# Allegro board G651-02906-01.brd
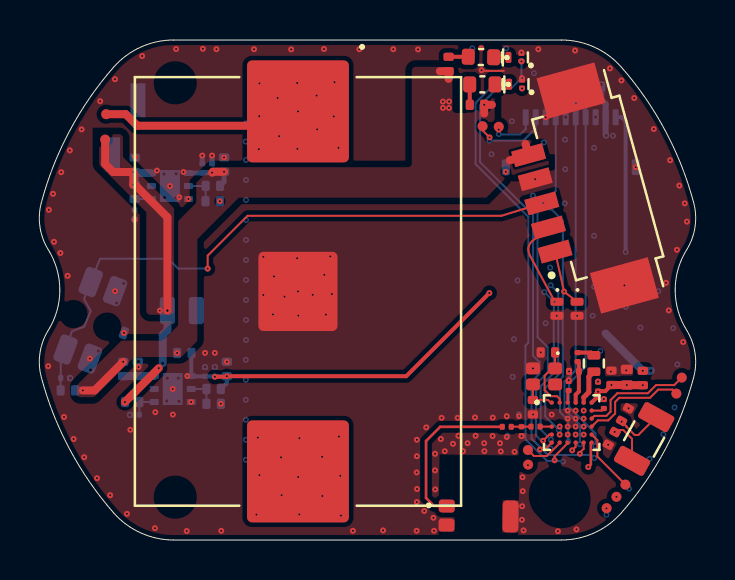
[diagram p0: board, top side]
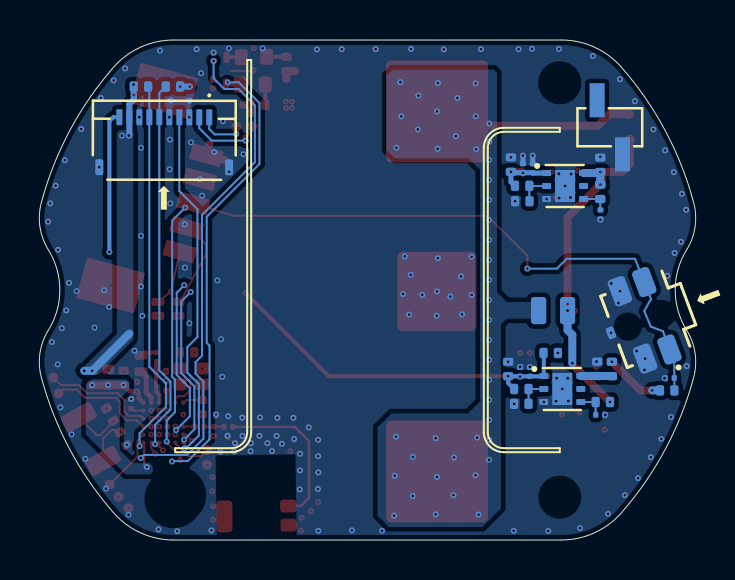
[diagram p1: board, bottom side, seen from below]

Outline 32.79 x 25 mm; copper layers: TOP, L2, L3, BOTTOM. Coordinates in mm from the lower left corner of the outline.
Outline path: 0.07,16.87 arc(1.49,20.46) 3.68,23.64 arc(5.04,24.64) 6.69,25 26.1,25 arc(27.75,24.64) 29.11,23.64 arc(31.3,20.46) 32.72,16.87 arc(32.79,15.65) 32.37,14.51 arc(31.79,12.5) 32.37,10.49 arc(32.79,9.35) 32.72,8.13 arc(31.3,4.54) 29.11,1.36 arc(27.75,0.36) 26.1,0 6.69,0 arc(5.04,0.36) 3.68,1.36 arc(1.49,4.54) 0.07,8.13 arc(0,9.35) 0.42,10.49 arc(0.99,12.5) 0.42,14.51 arc(0,15.65) 0.07,16.87

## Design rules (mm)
constraint set DEFAULT: min track width 0.1
net group 50_OHMS: nets MCU_ANT_OUT
net group HIGH_CURRENT_POWER: nets MCU_DCC MCU_DCC1 MCU_DEC4 PP3300_SENSORS_R
net group MODERATE_CURRENT_POWER: nets LED_STATUS1 LED_STATUS1_R LED_STATUS2 LED_STATUS2_R PP1800_SENSORS
nets with their own width: min track width 0.1; nets MCU_ANT_IN
nets with their own width: min track width 0.4; nets PP3300_SENSORS_MCU

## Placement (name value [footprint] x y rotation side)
A1  -  [ANT_325X165X115_W3008]  21.95 1.2 359.2 top
C1  12pF  [CAPC1005L]  29.28 6.27 241 top
C2  12pF  [CAPC1005L]  28.61 5.08 61.7 top
C5  0.1uF  [CAPC0603L]  28.22 6.8 90 top
C6  1uF  [CAPC0603L_TOL09]  26.73 8.43 180 top
C7  100pF  [CAPC0603L]  26.46 7.7 90 top
C8  12pF  [CAPC1005L]  25.42 9.38 180 top
C9  12pF  [CAPC1005L]  24.67 6.64 270 top
C10  1.2pF  [CAPC0603L]  24.1 5.44 270 top
C12  1uF  [CAPC1005L]  4.74 18.76 90 bottom
C13  1uF  [CAPC1005L]  9.21 18.77 90 bottom
C15  1uF  [CAPC1005L]  9.35 8.55 90 bottom
C16  1000pF  [CAPC0603L]  1.26 8.1 359.2 bottom
C17  4.7uF  [CAPC1005L_TOL15]  29.37 8.14 90 top
C18  1uF  [CAPC1005L]  28.6 8.11 90 top
C19  0.1uF  [CAPC0603L]  27.93 7.67 90 top
C20  0.1uF  [CAPC0603L]  8.61 18.59 90 bottom
C21  0.01uF  [CAPC0603L]  8.12 18.59 90 bottom
C22  0.1uF  [CAPC0603L]  8.75 8.41 90 bottom
C23  0.01uF  [CAPC0603L]  8.26 8.41 90 bottom
C24  1uF  [CAPC1005L]  4.89 8.56 90 bottom
D1  -  [SOD110X70X60L_SP1212]  25.87 11.56 270 top
D2  -  [SOD110X70X60L_SP1212]  26.88 11.56 270 top
DS1  GREEN  [LEDC1608L_TOL25]  22.14 22.78 180 top
DS2  GREEN  [LEDC1608L_TOL25]  22.07 24.15 178.8 top
J1  -  [KEYSTONE_3034TR]  12.91 12.43 270 top
J2  -  [MOLEX_53261-0571]  27.92 17.6 285.3 top
J3  -  [HIROSE_FH34SRJ-10S-0P5SH-50]  26.57 19.99 0.1 bottom
J4  -  [HARWIN_M50-3140245]  4.27 20.64 180 bottom
L1  15nH  [INDC0603L]  26.91 9.14 270 top
L2  10uH  [INDC1107L_TOL10]  27.72 8.83 90 top
L3  2.2nH  [INDC0603L]  24.8 5.67 180 top
L4  3.3nH  [INDC0603L]  23.36 5.66 180 top
NOREF  -  []  4.59 18.6 0 top
NOREF#2  -  []  10.36 0.88 90 top
NOREF#3  -  []  0.87 7.21 0 top
NOREF#4  -  []  0.91 8.02 0 top
NOREF#5  -  []  5.72 6.9 90 top
NOREF#6  -  []  28.09 6.95 0 top
NOREF#7  -  []  8.2 10.75 90 top
NOREF#8  -  []  4.47 19.29 0 top
NOREF#9  -  []  28.04 7.95 0 top
NOREF#10  -  []  27.17 22.51 0 top
NOREF#11  -  []  21.22 22.26 90 top
NOREF#12  -  []  7.96 18.91 0 top
NOREF#13  -  []  24.11 6.48 0 top
NOREF#14  -  []  25.78 14.42 0 top
NOREF#15  -  []  26.34 8.25 0 top
NOREF#16  -  []  23.25 23.8 90 top
NOREF#17  -  []  1.68 11.3 0 top
NOREF#18  -  []  6.7 9.62 0 top
NOREF#19  -  []  14.46 10.45 90 top
NOREF#20  -  []  28.31 21.14 0 top
NOREF#21  -  []  2.65 19.69 0 top
NOREF#22  -  []  4.47 17.93 0 top
NOREF#23  -  []  7 16.9 90 top
NOREF#24  -  []  23.94 -0.03 90 top
NOREF#25  -  []  28.05 4.92 0 top
NOREF#26  -  []  26.63 8.25 0 top
NOREF#27  -  []  8.17 7.08 0 top
NOREF#28  -  []  8.92 8.09 90 top
NOREF#29  -  []  21.35 21.48 90 top
NOREF#30  -  []  27.49 11.21 90 top
NOREF#31  -  []  9.2 8.39 0 top
NOREF#32  -  []  26.78 8.84 0 top
NOREF#33  -  []  29.27 5.68 90 top
NOREF#34  -  []  4.43 6.09 90 top
NOREF#35  -  []  7.75 9.07 90 top
NOREF#36  -  []  24.38 7.53 90 top
NOREF#37  -  []  25.98 22.51 0 top
NOREF#38  -  []  23.57 0.35 90 top
NOREF#39  -  []  23.92 16.1 0 top
NOREF#40  -  []  23.27 5.58 0 top
NOREF#41  -  []  28.46 4.92 0 top
NOREF#42  -  []  27.92 14.6 0 top
NOREF#43  -  []  6.14 6.75 0 top
NOREF#44  -  []  30.14 18.02 90 top
NOREF#45  -  []  9.06 18.61 0 top
NOREF#46  -  []  8.13 7.39 0 top
NOREF#47  -  []  4.59 17.25 0 top
NOREF#48  -  []  26.33 7.84 0 top
NOREF#49  -  []  5.8 16.96 0 top
NOREF#50  -  []  26.33 7.39 0 top
NOREF#51  -  []  24.46 19.24 0 top
NOREF#52  -  []  4.43 6.09 0 top
NOREF#53  -  []  5.58 17.05 90 top
NOREF#54  -  []  23.97 5.58 0 top
NOREF#55  -  []  23.28 22.46 90 top
NOREF#56  -  []  26.66 22.39 90 top
NOREF#57  -  []  7.77 6.75 90 top
NOREF#58  -  []  0.49 9.82 0 top
NOREF#59  -  []  26.53 12.11 0 top
NOREF#60  -  []  4.33 8.4 0 top
NOREF#61  -  []  30.82 15.5 90 top
NOREF#62  -  []  20.3 23.64 0 top
NOREF#63  -  []  30.14 18.02 90 top
NOREF#64  -  []  8.48 18.29 0 top
NOREF#65  -  []  8.78 18.27 90 top
NOREF#66  -  []  25.52 12.11 0 top
NOREF#67  -  []  8.54 6.65 0 top
NOREF#68  -  []  24.43 7.58 0 top
NOREF#69  -  []  27.51 9.2 0 top
NOREF#70  -  []  24.68 8.58 0 top
NOREF#71  -  []  8.48 18.73 0 top
NOREF#72  -  []  4.6 15.97 0 top
NOREF#73  -  []  9.08 9.07 0 top
NOREF#74  -  []  26.33 11.23 90 top
NOREF#75  -  []  20.73 23.27 90 top
NOREF#76  -  []  26.39 8.62 0 top
NOREF#77  -  []  27.77 7.99 0 top
NOREF#78  -  []  24.46 19.24 0 top
NOREF#79  -  []  8.13 6.65 0 top
NOREF#80  -  []  25.61 22.95 0 top
NOREF#81  -  []  30.14 18.02 90 top
NOREF#82  -  []  28.79 5.94 0 top
NOREF#83  -  []  26.3 8.02 0 top
NOREF#84  -  []  4.9 15.96 90 top
NOREF#85  -  []  24.9 9.11 90 top
NOREF#86  -  []  25.5 4.87 0 top
NOREF#87  -  []  8.09 17.55 0 top
NOREF#88  -  []  4.62 8.04 90 top
NOREF#89  -  []  28.1 8.23 90 top
NOREF#90  -  []  19.89 23.64 0 top
NOREF#91  -  []  8.43 8.09 90 top
NOREF#92  -  []  27.21 22.39 0 top
NOREF#93  -  []  5.94 6.81 0 top
NOREF#94  -  []  25.61 5.27 0 top
NOREF#95  -  []  4.57 15.96 0 top
NOREF#96  -  []  29.11 5.41 90 top
NOREF#97  -  []  39.01 18.06 90 top
NOREF#98  -  []  5.89 19.69 90 top
NOREF#99  -  []  8.54 7.39 0 top
NOREF#100  -  []  8.94 18.25 90 top
NOREF#101  -  []  29.12 18.91 90 top
NOREF#102  -  []  4.6 16.43 0 top
NOREF#103  -  []  1.24 7.32 0 top
NOREF#104  -  []  29.61 7.94 0 top
NOREF#105  -  []  26.6 8.98 0 top
NOREF#106  -  []  23.05 5.5 0 top
NOREF#107  -  []  29.7 7.57 90 top
NOREF#108  -  []  28.45 7.95 0 top
NOREF#109  -  []  29.63 3.96 90 top
NOREF#110  -  []  20.18 24.32 0 top
NOREF#111  -  []  28.61 4.49 0 top
NOREF#112  -  []  27.8 7.37 0 top
NOREF#113  -  []  4.81 1.78 90 top
NOREF#114  -  []  7.07 9.19 0 top
NOREF#115  -  []  27.8 7.82 0 top
NOREF#116  -  []  6.38 11.47 0 top
NOREF#117  -  []  28.74 4 0 top
NOREF#118  -  []  24.71 5.59 0 top
NOREF#119  -  []  5.35 16.65 0 top
NOREF#120  -  []  23.57 0.35 0 top
NOREF#121  -  []  24.1 23.95 90 top
NOREF#122  -  []  29.13 6.11 0 top
NOREF#123  -  []  24.49 5.5 0 top
NOREF#124  -  []  27.21 22.39 90 top
NOREF#125  -  []  24.45 5.59 0 top
NOREF#126  -  []  3.63 19.29 90 top
NOREF#127  -  []  23.25 24.45 0 top
NOREF#128  -  []  27.35 9.43 0 top
NOREF#129  -  []  27.23 8.98 90 top
NOREF#130  -  []  27.58 22.51 0 top
NOREF#131  -  []  21.31 21.6 0 top
NOREF#132  -  []  28.1 8.2 90 top
NOREF#133  -  []  5.45 16.65 0 top
NOREF#134  -  []  8.59 8.72 0 top
NOREF#135  -  []  8.17 7.28 90 top
NOREF#136  -  []  20.27 1.07 90 top
NOREF#137  -  []  4.21 10.15 90 top
NOREF#138  -  []  0.83 7.32 0 top
NOREF#139  -  []  8.08 16.78 0 top
NOREF#140  -  []  6.46 10.13 0 top
NOREF#141  -  []  25.61 5.27 0 top
NOREF#142  -  []  8.79 8.39 0 top
NOREF#143  -  []  21.35 22.04 0 top
NOREF#144  -  []  26.73 11.34 0 top
NOREF#145  -  []  9.22 6.54 90 top
NOREF#146  -  []  24.68 7.78 90 top
NOREF#147  -  []  23.45 24.13 0 top
NOREF#148  -  []  3.6 8.39 0 top
NOREF#149  -  []  4.39 6.18 0 top
NOREF#150  -  []  27.61 5.27 90 top
NOREF#151  -  []  8.49 16.78 0 top
NOREF#152  -  []  18.69 13.37 0 top
NOREF#153  -  []  25.52 11.01 90 top
NOREF#154  -  []  6 12.2 0 top
NOREF#155  -  []  4.09 6.62 90 top
NOREF#156  -  []  5.59 6.5 90 top
NOREF#157  -  []  28.09 6.5 0 top
NOREF#158  -  []  24.27 5.12 90 top
NOREF#159  -  []  29.83 21.59 90 top
NOREF#160  -  []  26.48 11.21 90 top
NOREF#161  -  []  4.74 8.4 0 top
NOREF#162  -  []  28.74 4 90 top
NOREF#163  -  []  4.81 1.78 0 top
NOREF#164  -  []  28.06 6.49 90 top
NOREF#165  -  []  8.94 19.3 0 top
NOREF#166  -  []  8.5 17.55 0 top
NOREF#167  -  []  26.53 11.01 90 top
NOREF#168  -  []  8.13 17.43 90 top
NOREF#169  -  []  1.8 9.07 0 top
NOREF#170  -  []  24.4 6.12 0 top
NOREF#171  -  []  7.14 6.75 90 top
NOREF#172  -  []  4.44 8.03 90 top
NOREF#173  -  []  27.61 5.67 90 top
NOREF#174  -  []  25.72 11.34 0 top
NOREF#175  -  []  30.82 15.5 90 top
NOREF#176  -  []  26.39 8.23 90 top
NOREF#177  -  []  24.31 21.13 0 top
NOREF#178  -  []  29.9 7.58 0 top
NOREF#179  -  []  4.18 18.6 0 top
NOREF#180  -  []  6 16.9 0 top
NOREF#181  -  []  21.16 24.69 0 top
NOREF#182  -  []  20.75 0.75 0 top
NOREF#183  -  []  1.58 7.93 90 top
NOREF#184  -  []  25.45 15.63 0 top
NOREF#185  -  []  23.12 21.04 0 top
NOREF#186  -  []  28.92 18.44 90 top
NOREF#187  -  []  24.4 6.12 90 top
NOREF#188  -  []  8.12 17.21 0 top
NOREF#189  -  []  25.27 9.22 0 top
NOREF#190  -  []  28.06 7.12 0 top
NOREF#191  -  []  10.93 10.7 0 top
NOREF#192  -  []  4.47 16.88 90 top
NOREF#193  -  []  25.28 22.68 0 top
NOREF#194  -  []  3.3 8.77 90 top
NOREF#195  -  []  27.87 4.62 90 top
NOREF#196  -  []  28.88 7.58 90 top
NOREF#197  -  []  23.97 5.13 0 top
NOREF#198  -  []  1.28 9.53 0 top
NOREF#199  -  []  7.63 16.9 90 top
NOREF#200  -  []  3.63 19.29 0 top
NOREF#201  -  []  5.45 16.65 90 top
NOREF#202  -  []  25.57 22.51 0 top
NOREF#203  -  []  30.02 13.9 0 top
NOREF#204  -  []  10.36 0.88 0 top
NOREF#205  -  []  4.65 6.18 0 top
NOREF#206  -  []  23.01 5.58 0 top
NOREF#207  -  []  22.99 21.96 0 top
NOREF#208  -  []  4.18 17.25 0 top
NOREF#209  -  []  26.03 7.58 90 top
NOREF#210  -  []  1.92 7.2 90 top
NOREF#211  -  []  24.86 9.22 0 top
NOREF#212  -  []  3.06 12.44 0 top
NOREF#213  -  []  8.62 8.55 0 top
NOREF#214  -  []  21.22 23.3 0 top
NOREF#215  -  []  27.77 7.36 90 top
NOREF#216  -  []  8.1 8.72 0 top
NOREF#217  -  []  4.62 9.09 0 top
NOREF#218  -  []  23.28 23.12 0 top
NOREF#219  -  []  6.66 9.19 0 top
NOREF#220  -  []  30.02 7.94 0 top
NOREF#221  -  []  8.29 18.27 90 top
NOREF#222  -  []  23.68 5.5 90 top
NOREF#223  -  []  23.48 22.79 0 top
NOREF#224  -  []  -490.9 -253.43 0 top
NOREF#225  -  []  21.14 23.64 90 top
NOREF#226  -  []  21.72 21.6 0 top
NOREF#227  -  []  1.17 8.02 0 top
NOREF#228  -  []  8.45 18.91 0 top
NOREF#229  -  []  29.22 7.98 0 top
NOREF#230  -  []  7.99 18.73 0 top
NOREF#231  -  []  26.78 9.29 0 top
NOREF#232  -  []  4.01 8.39 0 top
NOREF#233  -  []  4.09 6.62 0 top
NOREF#234  -  []  8.13 17.43 0 top
NOREF#235  -  []  29.83 18.39 90 top
NOREF#236  -  []  24.38 8.83 0 top
NOREF#237  -  []  29.05 8.71 0 top
NOREF#238  -  []  24.52 6.48 0 top
NOREF#239  -  []  27.34 11.23 90 top
NOREF#240  -  []  23.94 5.12 0 top
NOREF#241  -  []  3.89 8.03 0 top
NOREF#242  -  []  5.59 6.5 0 top
NOREF#243  -  []  7.99 18.29 0 top
NOREF#244  -  []  8.17 7.28 0 top
NOREF#245  -  []  4.47 18.23 90 top
NOREF#246  -  []  8.13 8.11 0 top
NOREF#247  -  []  26.3 7.38 90 top
NOREF#248  -  []  5.49 6.5 0 top
NOREF#249  -  []  28.33 8.63 0 top
NOREF#250  -  []  4.05 6.74 0 top
NOREF#251  -  []  8.65 18.61 0 top
NOREF#252  -  []  25.12 5.5 90 top
NOREF#253  -  []  9.08 8.03 90 top
NOREF#254  -  []  29.9 7.58 90 top
NOREF#255  -  []  8.13 8.55 0 top
NOREF#256  -  []  1.58 7.93 0 top
NOREF#257  -  []  9.17 16.66 90 top
NOREF#258  -  []  4.46 6.74 0 top
NOREF#259  -  []  24.13 22.62 90 top
NOREF#260  -  []  8.62 8.11 0 top
NOREF#261  -  []  23.52 21.04 0 top
NOREF#262  -  []  28.72 6.11 0 top
NOREF#263  -  []  23.94 -0.03 0 top
NOREF#264  -  []  24.9 9.65 0 top
Q1  -  [DFN3P35X65_105X65L_GSD]  23.8 22.79 180 top
Q2  -  [DFN3P35X65_105X65L_GSD]  23.77 24.13 180 top
R1  4.7K  [RESC1005L]  26.13 22.67 0 bottom
R2  4.7K  [RESC1005L]  27.73 22.67 180 bottom
R3  100K  [RESC1005L]  8.65 17.71 180 bottom
R4  17.8K  [RESC1005L]  8.64 16.94 0 bottom
R5  51K  [RESC1005L]  8.69 7.55 180 bottom
R6  19.1K  [RESC1005L]  8.69 6.81 0 bottom
R7  100K  [RESC1005L]  1.39 7.48 179.8 bottom
R8  3.3K  [RESC1005L]  21.87 21.76 180 top
R9  3.3K  [RESC1005L]  20.45 23.8 90 top
R10  2.2  [RESC2012L]  7.1 11.47 0 bottom
R11  2.7  [RESC1005L]  30.17 8.1 270 top
R12  0  [RESC1005L]  4.74 17.41 90 bottom
R13  0  [RESC1005L]  4.61 6.9 180 bottom
R17  10K  [RESC0603L]  4.73 16.28 270 bottom
R18  10K  [RESC0603L]  4.74 6.26 180 bottom
R19  0  [RESC1005L]  4.16 8.55 270 bottom
R20  0  [RESC1005L]  7.22 9.35 0 bottom
SW1  -  [SW_ALPS_SKSC_350X355_5P]  2.52 10.98 249.5 bottom
TP1  -  [TP050]  24.42 4.5 0 top
TP2  -  [TP050]  29.3 2.77 0 top
TP3  -  [TP050]  24.43 3.77 0 top
TP4  -  [TP050]  28.36 1.59 0 top
TP8  -  [TP050]  32.12 8.12 0 top
TP9  -  [TP050]  28.85 2.16 0 top
TP10  -  [TP050]  31.85 7.32 0 top
TP15  -  [TP050]  3.26 20.02 0 top
TP16  -  [TP050]  3.31 21.29 0 top
TP17  -  [TP050]  22.96 20.66 0 top
TP18  -  [TP050]  22.15 20.69 0 top
U1  -  [BGA33CP40_6X7_251X249N]  26.61 5.87 0 top
U2  -  [SON7P65_210X210T160X100L]  6.5 17.7 180 bottom
U3  -  [SON7P65_210X210T160X100L]  6.64 7.55 180 bottom
Y1  -  [XTALDFN2P235_330X160L130X65L]  30.24 5.05 241 top
Y2  -  [OSCCC170X130L50X55L]  25.23 8.18 180 top

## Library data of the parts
A1 = ANTENNA: User Part Number: G120-00035-00; alternate symbols: (ANT_325X165X115_W3008_MIR); part number: ANTENNA-120-00035-00
C1 C2 C8 C9 = CAP: alternate symbols: (CAPC1005L_LPI,CAPC1005N); part number: CAP-150-01169-00
C5 C19 C20 C22 = CAP: alternate symbols: (CAPC0603L_LPI,CAPC0603L_FLEX,CAPC0603L_SMD,CAPC0603N); part number: CAP-150-00007-00
C6 = CAP: alternate symbols: (CAPC0603L_TOL09_LPI); part number: CAP-150-00485-00
C7 = CAP: alternate symbols: (CAPC0603L_LPI,CAPC0603L_FLEX,CAPC0603L_SMD,CAPC0603N); part number: CAP-150-00118-00
C10 = CAP: alternate symbols: (CAPC0603L_LPI,CAPC0603L_FLEX,CAPC0603N); part number: CAP-150-06049-00
C12 C13 C15 C18 C24 = CAP: alternate symbols: (CAPC1005L_LPI,CAPC1005N); part number: CAP-150-00009-00
C16 = CAP: alternate symbols: (CAPC0603L_LPI,CAPC0603L_FLEX,CAPC0603N); part number: CAP-150-00029-00
C17 = CAP: alternate symbols: (CAPC1005L_TOL15_LPI); part number: CAP-150-00039-00
C21 C23 = CAP: alternate symbols: (CAPC0603L_LPI,CAPC0603L_FLEX,CAPC0603N); part number: CAP-150-00027-00
D1 D2 = TVS: part number: TVS-480-01472-00
DS1 DS2 = LED: part number: LED-246-00025-00,DEFAULT
J1 = CHARGE_CONTACT: alternate symbols: (); part number: CHARGE_CONTACT-670-00710-00,DEFAULT
J2 = W2B_5PIN: part number: W2B_5PIN-210-05314-00
J3 = FFC_10PIN: User Part Number: G210-00407-00; part number: FFC_10PIN-210-00407-00,DEFAULT
J4 = HDR_1X2: part number: HDR_1X2-210-03654-00
L1 = INDUCTOR: alternate symbols: (INDC0603L,INDC0603L_LPI); part number: INDUCTOR-180-00327-00,DEFAULT
L2 = INDUCTOR: User Part Number: G180-04741-00; part number: INDUCTOR-180-04741-00,DEFAULT
L3 = INDUCTOR: alternate symbols: (INDC0603N,INDC0603L_LPI); part number: INDUCTOR-180-00550-00,DEFAULT
L4 = INDUCTOR: alternate symbols: (INDC0603N,INDC0603L_LPI); part number: INDUCTOR-180-00556-00,DEFAULT
Q1 Q2 = NMOS: part number: NMOS-480-01298-00
R1 R2 = RES: alternate symbols: (RESC1005L_LPI,RESC1005N); part number: RES-470-00546-00
R3 = RES: alternate symbols: (RESC1005L_LPI,RESC1005N); part number: RES-470-00580-00
R4 = RES: alternate symbols: (RESC1005L_LPI,RESC1005N); part number: RES-470-01541-00
R5 = RES: alternate symbols: (RESC1005L_LPI,RESC1005N); part number: RES-470-00824-00
R6 = RES: alternate symbols: (RESC1005L_LPI,RESC1005N); part number: RES-470-01558-00
R7 = RES: alternate symbols: (RESC1005L_LPI,RESC1005N); part number: RES-470-00545-00
R8 R9 = RES: alternate symbols: (RESC1005L_LPI,RESC1005N); part number: RES-470-00350-00
R10 = RES: User Part Number: G470-02564-00; alternate symbols: (RESC2012N); part number: RES-470-02564-00
R11 = RES: alternate symbols: (RESC1005L_LPI,RESC1005N); part number: RES-470-00372-00
R12 R13 R19 R20 = RES: alternate symbols: (RESC1005L_LPI,RESC1005N); part number: RES-470-03443-00
R17 R18 = RES: alternate symbols: (RESC0603L_LPI); part number: RES-470-00033-00
SW1 = SPST: User Part Number: G510-00432-00; part number: SPST-510-00432-00
TP1-TP4 TP8-TP10 TP15-TP18 = TESTPOINT: alternate symbols: (TP50_LPI, TP35, TP50_KO110, TP90M100_KO300); part number: TESTPOINT-000-76849-00
U1 = NRF52810: User Part Number: G313-08600-00; part number: NRF52810-313-08600-00
U2 U3 = ADP123A: part number: ADP123A-313-08595-00
Y1 = XTAL: User Part Number: G230-00144-00; alternate symbols: (DFN320X150X85-2L); part number: XTAL-230-00144-00
Y2 = XTAL: part number: XTAL-230-00166-00

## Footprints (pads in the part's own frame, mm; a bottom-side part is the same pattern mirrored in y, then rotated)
ANT_325X165X115_W3008
  rrect 0.8x0.65 smd: 1(-1.6,0.475) 2(-1.6,-0.475)
  rrect 0.8x1.6 smd: 3(1.6,0)
BGA33CP40_6X7_251X249N
  round 0.22 smd: A1(-1,1) A2(-0.6,1) A3(-0.2,1) A4(0.2,1) A5(0.6,1) A6(1,1) B3(-0.2,0.6) B4(0.2,0.6) B5(0.6,0.6) B6(1,0.6) C1(-1,0.4) D3(-0.2,0.2) D4(0.2,0.2) D5(0.6,0.2) D6(1,0.2) E1(-1,-0.2) E2(-0.6,-0.2) E3(-0.2,-0.2) E4(0.2,-0.2) E5(0.6,-0.2) E6(1,-0.2) F1(-1,-0.6) F2(-0.6,-0.6) F3(-0.2,-0.6) F4(0.2,-0.6) F5(0.6,-0.6) F6(1,-0.6) G1(-1,-1) G2(-0.6,-1) G3(-0.2,-1) G4(0.2,-1) G5(0.6,-1) G6(1,-1)
CAPC0603L
  custom 0.065x0.065 smd: 1(-0.225,0) 2(0.225,0)
CAPC0603L_TOL09
  rrect 0.3x0.35 smd: 1(-0.245,0) 2(0.245,0)
CAPC1005L
  rrect 0.41x0.52 smd: 1(-0.36,0) 2(0.36,0)
CAPC1005L_TOL15
  rrect 0.47x0.6 smd: 1(-0.39,0) 2(0.39,0)
DFN3P35X65_105X65L_GSD
  rrect 0.3x0.55 smd: D(0.325,0)
  rrect 0.3x0.2 smd: G(-0.325,0.175) S(-0.325,-0.175)
HARWIN_M50-3140245
  rect 0.75x1.7 smd: 1(-0.635,1.35) 2(0.635,-1.35)
HIROSE_FH34SRJ-10S-0P5SH-50
  rrect 0.3x0.8 smd: 1(-2.25,-1.15) 2(-1.75,-1.15) 3(-1.25,-1.15) 4(-0.75,-1.15) 5(-0.25,-1.15) 6(0.25,-1.15) 7(0.75,-1.15) 8(1.25,-1.15) 9(1.75,-1.15) 10(2.25,-1.15)
  rrect 0.4x0.8 smd: G1(-3.25,1.35) G2(3.25,1.35)
INDC0603L
  custom 0.065x0.065 smd: 1(-0.225,0) 2(0.225,0)
INDC1107L_TOL10
  rrect 0.43x0.65 smd: 1(-0.41,0) 2(0.41,0)
KEYSTONE_3034TR
  rrect 5.1x5.1 smd: 1(-9,0) 3(9,0)
  rrect 3.96x3.96 smd: 2(0,0)
LEDC1608L_TOL25
  rrect 0.65x0.8 smd: A(0.635,0) K(-0.635,0)
MOLEX_53261-0571
  rect 0.8x1.6 smd: 1(2.5,-2.9) 2(1.25,-2.9) 3(0,-2.9) 4(-1.25,-2.9) 5(-2.5,-2.9)
  rect 2.1x3 smd: M1(5.05,0) M2(-5.05,0)
OSCCC170X130L50X55L
  rrect 0.7x0.6 smd: 1(-0.555,-0.4) 2(0.555,-0.4) 3(0.555,0.4) 4(-0.555,0.4)
RESC0603L
  custom 0.065x0.065 smd: 1(-0.225,0) 2(0.225,0)
RESC1005L
  rrect 0.41x0.52 smd: 1(-0.36,0) 2(0.36,0)
RESC2012L
  rrect 0.76x1.36 smd: 1(-0.725,0) 2(0.725,0)
SOD110X70X60L_SP1212
  rrect 0.4x0.65 smd: A(0.35,0) K(-0.35,0)
SON7P65_210X210T160X100L
  rrect 0.45x0.3 smd: 1(-0.925,0.65) 2(-0.925,0) 3(-0.925,-0.65) 4(0.925,-0.65) 5(0.925,0) 6(0.925,0.65)
  rect 1x1.6 smd: 7(0,0)
SW_ALPS_SKSC_350X355_5P
  round 0 hole 0.8 unplated: (0,0.9) (0,-0.9)
  custom 0.225x0.225 smd: 1(1.8,0.65) 2(-1.8,0.65) 3(1.8,-0.65) 4(-1.8,-0.65)
  rrect 0.6x0.4 smd: 5(0,-1.8)
TP050
  round 0.5 smd: 1(0,0)
XTALDFN2P235_330X160L130X65L
  rrect 0.9x1.7 smd: 1(-1.25,0) 2(1.25,0)

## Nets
GND: A1.2 A1.3 C1.1 C2.1 C5.2 C6.2 C7.2 C8.2 C9.2 C10.2 C12.2 C13.2 C15.2 C16.2 C17.2 C18.2 C19.2 C20.2 C21.2 C22.2 C23.2 C24.2 D1.A D2.A J1.2 J2.4 J2.M1 J2.M2 J3.3 J3.5 J3.8 J3.G1 J3.G2 J4.2(P2) Q1.S Q2.S R4.2 R6.2 R17.2 R18.2 SW1.3 SW1.4 SW1.5(GND) U1.B3 U1.B4 U1.C1 U1.D3 U1.D4 U1.E3 U1.E4 U2.3 U2.7 U3.3 U3.7 Y2.2
CAPSENSE_RESET_MCU: J3.4 U1.G3
J3_UNUSED_PIN1: J3.1 TP17.1(A)
J3_UNUSED_PIN2: J3.2 TP18.1(A)
LED_STATUS1: DS1.K Q1.D
LED_STATUS1_R: DS1.A R8.2
LED_STATUS2: DS2.K Q2.D
LED_STATUS2_R: DS2.A R9.2
MCU_ANT_IN: L3.1 U1.E1
MCU_ANT_MATCH: C10.1 L3.2 L4.1
MCU_ANT_OUT: A1.1(RF) L4.2
MCU_DCC: L2.1 U1.A5
MCU_DCC1: L1.1 L2.2
MCU_DEC1: C5.1 U1.B6
MCU_DEC2: C7.1 U1.A3
MCU_DEC4: C6.1 L1.2 U1.A4
MCU_P003: TP8.1(A) U1.D6
MCU_P004: TP9.1(A) U1.E5
MCU_P005: TP10.1(A) U1.E6
MCU_P008: TP2.1(A) U1.F6
MCU_P018: TP3.1(A) U1.E2
MCU_P020: TP1.1(A) U1.G2
MCU_PO17: TP4.1(A) U1.F3
MCU_RESET: C16.1 J2.3 R7.2 SW1.1 SW1.2 U1.F2
MCU_STATUS1: Q1.G U1.G4
MCU_STATUS2: Q2.G U1.F4
MCU_SWDCLK: D1.K J2.2 U1.G1
MCU_SWDIO: D2.K J2.1 U1.F1
MCU_XL1: C1.2 U1.B5 Y1.1
MCU_XL2: C2.2 U1.D5 Y1.2
PP1800_EN: R13.1 R18.1 U3.4
PP1800_SENSORS: C15.1 C22.1 C23.1 J3.10 R5.1 R20.2 U3.1(VOUT)
PP3300_EN: R12.1 R17.1 U2.4
PP3300_SENSORS: C13.1 C20.1 C21.1 J2.5 J3.9 R1.1 R2.1 R3.1 R7.1 R8.1 R9.1 R11.1 R19.1 R20.1 U2.1(VOUT)
PP3300_SENSORS_MCU: C17.1 C18.1 C19.1 R11.2 U1.A6 U1.G6
PP3300_SENSORS_R: C24.1 R19.2 U3.6
PP_1800_ADJ: R5.2 R6.1 U3.2
PP_3300_ADJ: R3.2 R4.1 U2.2
PP_VBAT: C12.1 R10.1 R12.2 R13.2 TP15.1(A) U2.6
PP_VBAT_SENSE: J1.1 J1.3(S<3>) J4.1 R10.2 TP16.1(A)
SCL_3300: J3.6 R1.2 U1.G5
SDA_3300: J3.7 R2.2 U1.F5
XC1: C9.1 U1.A1 Y2.3
XC2: C8.1 U1.A2(XC2) Y2.1

Pads without a net: U2 5; U3 5; Y2 4

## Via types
v1: diameter 0.3, hole 0.1, TOP to L2, 234 vias
v2: diameter 0.4, hole 0.2, L2 to L3, 231 vias
v3: diameter 0.3, hole 0.15, L3 to BOTTOM, 252 vias

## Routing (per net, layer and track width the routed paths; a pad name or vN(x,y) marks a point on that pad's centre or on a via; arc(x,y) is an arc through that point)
GND: length 74.4
  TOP w0.1: 23.22,23.46 22.14,23.46 v1(22.1,23.49) ; 24.1,24.3 v3(24.1,24.38) ; C5.2 v3(28.22,7.05) ; Q1.S v1(24.13,23.09)
  TOP w0.127: C7.2 v1(26.46,7.99)
  L2 w0.1: v2(0.42,16.16) v3(0.44,16.51) ; v2(23.75,5.17) 23.77,5.19 v1(24.1,5.19) ; v1(26.88,11.21) v2(27.23,11.21) ; v2(2.24,20.84) v3(2.08,20.53) ; v1(29.25,12.73) v2(29.58,12.86) ; v2(32.28,9.56) v3(32.19,9.9) ; v2(2.41,3.85) v3(2.21,4.14) ; v2(4.52,5.87) 4.52,5.51 v1(4.52,5.51) ; v2(16.01,0.46) v3(15.66,0.46) ; v2(3.11,2.85) v3(2.85,3.09) ; v2(4.07,10.03) v3(4.21,10.35) ; v2(31.38,13.28) 31.41,13.2 v3(31.33,12.86) ; v2(1.66,19.81) 1.65,19.79 v3(1.49,19.48) ; v2(4.93,9.27) v1(4.93,8.65) ; v1(26.82,21.84) 26.62,21.64 v2(26.47,21.64) ; v2(1.44,12.86) v3(1.38,13.21) ; v3(28.44,4.76) v2(28.77,4.63) ; v2(4.82,24) v3(5.11,24.2) ; v2(2.22,8.8) 2.42,8.88 v3(2.5,9.07) ; v1(24.13,23.09) v2(24.48,23.09) ; v2(4.64,1.1) v3(4.35,1.31) ; v2(28.26,23.81) v3(28.53,23.58) ; v2(30.9,20.25) v3(30.72,20.55) ; v1(24.68,8.58) v2(24.33,8.58) ; v2(3.17,22.25) v3(3.01,21.94) ; v3(24.79,18.04) v2(24.47,17.9) ; v2(27.12,24.39) v3(26.78,24.47) ; v2(16.33,24.54) v3(15.98,24.54) ; v2(25.31,20.79) v3(25.31,21.14) ; v2(12.92,24.53) v3(12.57,24.53) ; v2(29.28,22.68) v3(29.1,22.98) ; v2(1.19,18.72) v3(1.06,18.39) ; v2(25.57,0.45) v3(25.92,0.44) ; v1(26.49,8.43) v2(26.49,8.78) ; v2(9.18,24.54) v3(8.83,24.54) ; v1(25.61,6.27) v2(25.96,6.27) ; v2(23.7,18.41) v3(23.32,18.41) ; v1(29.46,6.58) v2(29.14,6.72) ; v2(29.92,21.8) v3(29.74,22.1) ; v2(19.27,24.53) v3(18.92,24.53) ; v2(7.81,24.54) v3(8.15,24.56) ; v2(9.35,16.94) v3(9,16.94) ; v2(9.42,0.46) v3(9.07,0.46) ; v2(32.02,14.83) v3(31.88,14.51) ; v3(24.1,24.38) v2(24.45,24.38) ; v2(0.48,8.35) v3(0.41,8.69) ; v2(27.19,0.63) v3(26.85,0.53) ; v1(25.87,11.21) v2(25.52,11.21) ; v2(32.1,17.38) v3(32,17.72) ; v2(19.2,0.46) v3(18.85,0.46) ; v2(7.69,0.45) v3(7.34,0.45) ; v2(11.06,24.54) v3(10.71,24.54) ; v2(17.52,0.48) v3(17.17,0.48) ; v2(6.5,17.35) v3(6.5,17.7) ; v1(25.06,9.38) v2(24.71,9.38) ; v2(14.56,24.55) v3(14.21,24.55) ; v2(1.18,14.03) v3(1.02,14.35) ; v2(25.29,24.54) v3(24.94,24.54) ; v2(6.1,0.51) v3(5.75,0.59) ; v2(0.78,17.64) v3(0.65,17.31) ; v2(32.32,16.48) v3(32.27,16.83) ; v2(7.43,16.7) v3(7.43,17.05) ; v2(24.55,0.48) v3(24.2,0.48) ; v2(18.03,24.54) v3(17.68,24.54) ; v2(1.36,5.84) v3(1.2,6.15) ; v2(31.56,11.14) v3(31.47,11.48) ; v2(29.82,18.29) v3(29.82,18.64) ; v1(24.67,6.28) v2(24.32,6.28) ; v2(1.88,4.76) v3(1.68,5.05) ; v2(31.64,18.65) v3(31.54,18.99) ; v2(6.47,24.53) v3(6.81,24.55) ; 3.63,12.12 v3(3.76,12.44) ; v3(28.22,7.05) v2(28.22,6.7) ; v2(32.3,15.58) v3(32.38,15.92) ; v2(3.77,2) v3(3.51,2.24) ; v2(0.57,15.23) v3(0.7,14.91) ; v2(3.99,23.3) v3(3.75,23.04)
  L2 w0.25: v2(6.64,7.2) v3(6.64,7.55) ; v2(9.05,6.46) v3(9.05,6.81) ; v2(9.21,19.48) v3(9.21,19.13) ; v3(12.87,14.09) v2(12.87,13.74) ; v2(8.26,9) v1(8.26,9.36) ; v2(7.72,19.22) v1(8.12,19.22) ; v2(9.35,9.26) v3(9.35,8.91) ; v3(12.93,11.22) v2(12.93,10.87) ; v2(12.91,12.78) v3(12.91,12.43) ; v2(7.57,6.55) v3(7.57,6.9) ; v3(11.18,12.25) v2(11.18,11.9) ; v2(8.61,19.6) v1(8.61,19.22) ; v3(13.65,12.26) v2(13.65,11.91) ; v3(14.61,12.3) v2(14.61,11.95) ; v2(4.74,19.51) v3(4.74,19.16) ; v2(8.75,9) v1(8.75,9.36) ; v3(14.53,14.18) v2(14.53,13.83) ; v3(11.66,11.28) v2(11.66,10.93) ; v3(14.31,11.27) v2(14.31,10.92) ; v2(4.73,15.65) v3(4.73,16.01) ; v3(14.23,13.26) v2(14.23,12.91) ; v3(12.24,12.17) v2(12.24,11.82) ; v2(11.71,12.83) v3(11.71,13.18) ; v3(11.18,14.16) v2(11.18,13.81)
  L3 w0.1: v3(8.83,24.54) v2(9.18,24.54) ; v3(32.27,16.83) v2(32.32,16.48) ; v3(4.93,8.92) v2(4.93,9.27) ; v3(12.57,24.53) v2(12.92,24.53) ; v2(24.47,17.9) v3(24.79,18.04) ; v3(7.34,0.45) v2(7.69,0.45) ; v2(28.77,4.63) v3(28.44,4.76) ; v3(28.53,23.58) v2(28.26,23.81) ; v3(17.68,24.54) v2(18.03,24.54) ; v3(26.24,21.98) 26.47,21.74 v2(26.47,21.64) ; v3(1.49,19.48) 1.65,19.79 ; v3(32.19,9.9) v2(32.28,9.56) ; v3(29.1,22.98) v2(29.28,22.68) ; v3(18.85,0.46) v2(19.2,0.46) ; v3(24.2,0.48) v2(24.55,0.48) ; v3(1.68,5.05) v2(1.88,4.76) ; v3(0.7,14.91) v2(0.57,15.23) ; v3(6.81,24.55) v2(6.47,24.53) ; v3(1.06,18.39) v2(1.19,18.72) ; v3(27.81,21.14) v2(27.68,20.82) ; 23.32,18.59 v3(23.32,18.41) v2(23.7,18.41) ; v3(31.88,14.51) v2(32.02,14.83) ; v3(8.15,24.56) v2(7.81,24.54) ; v3(4.49,6.25) 4.52,6.22 v2(4.52,5.87) ; v3(3.75,23.04) v2(3.99,23.3) ; v3(17.17,0.48) v2(17.52,0.48) ; v3(2.53,8.5) 2.23,8.8 v2(2.22,8.8) 2.5,9.07 v3(2.5,9.07) ; v2(25.52,11.21) v3(25.31,10.84) ; v3(23.4,5.21) 23.71,5.21 v2(23.75,5.17) ; v3(24.94,24.54) v2(25.29,24.54) ; v3(32,17.72) v2(32.1,17.38) ; v3(26.85,0.53) v2(27.19,0.63) ; v3(3.51,2.24) v2(3.77,2) ; v3(6.5,17.7) v2(6.5,17.35) ; v3(1.38,13.21) v2(1.44,12.86) ; v2(24.32,6.28) v3(23.97,6.28) ; v3(2.08,20.53) v2(2.24,20.84) ; v3(30.72,20.55) v2(30.9,20.25) ; v3(4.21,10.35) v2(4.07,10.03) ; v3(10.71,24.54) v2(11.06,24.54) ; v3(4.35,1.31) v2(4.64,1.1) ; v3(32.38,15.92) v2(32.3,15.58) ; v3(2.85,3.09) v2(3.11,2.85) ; v2(24.45,24.38) v3(24.1,24.38) ; v3(31.54,18.99) v2(31.64,18.65) ; v2(27.23,11.21) v3(27.66,11.21) ; v3(0.41,8.69) v2(0.48,8.35) ; v3(26.78,24.47) v2(27.12,24.39) ; v2(29.58,12.86) v3(29.58,12.49) ; v3(3.83,11.85) v2(3.58,12.12) v3(3.76,12.44) ; v3(0.44,16.51) v2(0.42,16.16) ; v3(9,16.94) v2(9.35,16.94) ; v2(28.22,6.7) v3(28.22,7.05) ; v3(29.82,18.64) v2(29.82,18.29) ; v3(25.92,0.44) v2(25.57,0.45) ; v3(1.2,6.15) v2(1.36,5.84) ; v3(14.21,24.55) v2(14.56,24.55) ; v3(9.07,0.46) v2(9.42,0.46) ; v3(5.75,0.59) v2(6.1,0.51) ; v3(25.31,21.14) v2(25.31,20.79) ; v2(24.48,23.09) v3(24.73,23.34) ; v3(31.47,11.48) v2(31.56,11.14) ; v3(29.74,22.1) v2(29.92,21.8) ; v3(2.21,4.14) v2(2.41,3.85) ; v3(26.31,21.14) v2(26.31,20.79) ; v3(3.01,21.94) v2(3.17,22.25) ; v3(1.02,14.35) v2(1.18,14.03) ; v3(0.65,17.31) v2(0.78,17.64) ; v3(7.43,17.05) v2(7.43,16.7) ; v3(5.11,24.2) v2(4.82,24) ; v3(15.98,24.54) v2(16.33,24.54) ; v3(15.66,0.46) v2(16.01,0.46) ; v3(31.33,12.86) 31.41,13.2 ; v3(18.92,24.53) v2(19.27,24.53)
  L3 w0.25: v3(6.64,7.55) v2(6.64,7.2) ; v2(12.87,13.74) v3(12.87,14.09) ; v2(11.18,13.81) v3(11.18,14.16) ; v2(12.24,11.82) v3(12.24,12.17) ; v3(8.75,8.65) v2(8.75,9) ; v3(8.12,19.22) v1(8.12,19.22) v2(7.72,19.22) ; v3(4.74,19.16) v2(4.74,19.51) ; v2(11.18,11.9) v3(11.18,12.25) ; v3(8.61,19.22) v2(8.61,19.6) ; v3(7.57,6.9) v2(7.57,6.55) ; v2(14.53,13.83) v3(14.53,14.18) ; v3(14.61,12.3) v2(14.61,11.95) ; v3(9.05,6.81) v2(9.05,6.46) ; v3(4.73,16.01) v2(4.73,15.65) ; v3(13.65,12.26) v2(13.65,11.91) ; v3(9.35,8.91) v2(9.35,9.26) ; v3(9.21,19.13) v2(9.21,19.48) ; v3(14.31,11.27) v2(14.31,10.92) ; v2(14.23,12.91) v3(14.23,13.26) ; v2(11.71,12.83) v3(11.71,13.18) ; v2(11.66,10.93) v3(11.66,11.28) ; v3(12.91,12.43) v2(12.91,12.78) ; v2(12.93,10.87) v3(12.93,11.22) ; v3(8.26,8.65) v2(8.26,9)
  BOTTOM w0.1: C24.2 v3(4.93,8.92) ; J3.G1 v3(23.32,18.41)
  BOTTOM w0.25: C12.2 v3(4.74,19.16) ; 8.61,18.82 v3(8.61,19.22) ; 8.12,18.82 v3(8.12,19.22)
  vias: v1(5.77,6.39) v1(5.85,18.47) v1(6.65,6.27) v1(6.97,17.14) v1(7.18,18.4) v1(7.37,8.2) v1(18.86,5.01) v1(18.86,4.19) v1(18.85,3.38) v1(18.87,2.55) v1(18.86,1.9) v1(19.23,1.45) v1(19.33,5.63) v1(19.69,1.11) v1(19.72,0.46) v1(19.77,4.31) v1(19.77,3.48) v1(19.78,2.53) v1(20.1,6.11) v1(20.06,5.05) v1(20.26,4.44) v1(20.67,4.81) v1(20.9,6.11) v1(20.94,5.21) v1(21.17,4.44) v1(21.4,4.84) v1(21.77,6.13) v1(21.8,5.21) v1(22.08,24.59) v1(22.23,4.84) v1(22.24,4.44) v1(22.66,6.12) v1(22.65,5.2) v1(23.02,4.84) v1(23.06,4.43) v1(23.36,6.19) v1(23.36,5.15) v1(23.75,4.41) v1(23.98,6.19) v1(24.13,1.69) v1(24.12,1.01) v1(24.15,3.14) v1(24.16,2.44) v1(26.41,6.47) v1(26.41,6.07) v1(26.41,5.67) v1(26.81,6.47) v1(26.81,6.07) v1(26.81,5.67) v1(27.93,7.92) v1(28.57,8.42) v1(29.34,8.48) v2(0.53,9.47) v2(0.85,7.18) v2(1,10.51) v2(5.97,16.86) v2(6.1,7.77) v2(6.05,6.69) v2(6.14,18.7) v2(6.92,18.69) v2(6.85,16.75) v2(6.86,6.56) v2(7.23,7.86) v2(10.29,0.48) v2(11.77,0.46) v2(14.05,0.46) v2(16.73,5.75) v2(16.73,2.67) v2(16.84,4.49) v2(17.07,3.68) v2(17.13,1.36) v2(17.21,7.33) v2(17.38,5.14) v2(17.63,2.7) v2(17.8,6.56) v2(17.81,3.51) v2(18.04,5.93) v2(17.95,4.71) v2(18.14,0.98) v2(18.33,7.51) v2(18.41,1.77) v2(18.51,5.26) v2(18.46,4.19) v2(18.48,3.35) v2(18.47,2.55) v2(18.62,6.76) v2(18.94,1.12) v2(18.97,5.98) v2(19.31,6.85) v2(19.59,8.48) v2(19.77,2.99) v2(19.89,6.52) v2(19.9,4.69) v2(20.31,7.57) v2(20.88,6.51) v2(21.01,8.52) v2(21.27,24.54) v2(21.63,4.54) v2(21.76,7.33) v2(21.8,6.55) v2(22.23,8.07) v2(22.61,6.57) v2(22.61,4.69) v2(22.96,24.53) v2(23.42,4.73) v2(23.59,6.92) v2(24.76,6.9) v2(24.75,3.26) v2(24.86,1.03) v2(27.69,1.85) v2(27.99,1.06) v2(28.45,3.14) v2(28.96,8.66) v2(29.71,2.92) v2(30.69,4.41) v2(31,4.96) v3(1.52,8.09) v3(2.92,9.45) v3(4.19,12.83) v3(6.2,18.3) v3(6.23,17.12) v3(6.34,6.95) v3(6.37,8.09) v3(6.81,18.31) v3(6.8,17.1) v3(6.92,8.09) v3(6.95,6.94) v3(18.86,5.01) v3(18.86,4.19) v3(18.85,3.38) v3(18.87,2.55) v3(19.33,5.63) v3(19.77,4.31) v3(19.77,3.48) v3(19.78,2.53) v3(20.1,6.11) v3(20.06,5.05) v3(20.67,4.81) v3(20.9,6.11) v3(20.94,5.21) v3(21.17,4.44) v3(21.4,4.84) v3(21.64,24.58) v3(21.77,6.13) v3(21.8,5.21) v3(22.23,4.84) v3(22.24,4.44) v3(22.6,19.29) v3(22.66,6.12) v3(22.65,5.2) v3(23.02,4.84) v3(23.06,4.43) v3(23.33,24.58) v3(23.36,6.19) v3(23.62,20.94) v3(23.72,10.04) v3(23.66,8.16) v3(23.75,4.41) v3(23.9,12.98) v3(24.06,19.4) v3(24.67,17.22) v3(25.22,19.88) v3(25.3,21.97) v3(25.53,13.62) v3(25.54,15.78) v3(26.28,20.02) v3(26.29,18.54) v3(26.26,16.83) v3(27.73,19.61) v3(27.73,15.21) v3(27.73,12.67) v3(28.05,9.46) v3(28.35,1.26) v3(29.32,11.66) v3(29.48,2.57) v3(30.05,10.62) v3(30.51,4.06) v3(30.95,12.44) v3(31.2,5.28) v3(31.69,10.59) v3(31.76,6.63) v3(31.9,8.78)
CAPSENSE_RESET_MCU: length 20.1
  TOP w0.1: v1(25.76,3.99) 25.76,4.19 26.41,4.84 U1.G3
  L2 w0.1: v1(25.76,3.99) v2(25.44,3.82)
  L3 w0.1: v3(25.56,4.58) 25.56,3.96 25.44,3.84 v2(25.44,3.82)
  BOTTOM w0.1: J3.4 25.81,17.45 24.9,16.54 24.9,10.15 25.41,9.64 25.41,8.37 24.83,7.79 24.83,5.22 25.47,4.58 v3(25.56,4.58)
J3_UNUSED_PIN1: length 3
  L2 w0.1: v2(22.96,20.87) v1(22.96,20.52)
  L3 w0.1: v3(22.96,20.3) v2(22.96,20.87)
  BOTTOM w0.1: J3.1 24.31,20.55 24.04,20.28 22.98,20.28 v3(22.96,20.3)
J3_UNUSED_PIN2: length 4.7
  TOP w0.1: v1(22.5,20.13) 22.15,20.48 TP18.1
  L2 w0.1: v2(22.5,20.48) v1(22.5,20.13)
  L3 w0.1: v2(22.5,20.48) 22.5,19.98 v3(22.49,19.97)
  BOTTOM w0.1: J3.2 24.81,20.59 24.19,19.97 v3(22.49,19.97)
LED_STATUS1: length 0.7
  TOP w0.2: DS1.K 23.47,22.78 Q1.D
LED_STATUS1_R: length 1
  TOP w0.2: DS1.A R8.2
LED_STATUS2: length 0.7
  TOP w0.2: 22.71,24.14 23.44,24.14 Q2.D
LED_STATUS2_R: length 1
  TOP w0.2: R9.2 21.44,24.16 21.44,24.16
MCU_ANT_IN: length 0.6
  TOP w0.1: L3.1 U1.E1
MCU_ANT_MATCH: length 1
  TOP w0.1: 23.59,5.66 23.59,5.67 C10.1 24.57,5.67 L3.2
MCU_ANT_OUT: length 8.2
  TOP w0.13: A1.1 19.72,1.71 19.32,2.1 19.32,4.95 20.03,5.66 L4.2
MCU_DCC: length 1.8
  TOP w0.2: U1.A5 27.21,7.13
  TOP w0.25: 27.21,7.13 27.47,7.39 27.47,8.17 L2.1
MCU_DCC1: length 0.9
  TOP w0.2: L2.2 27.59,9.37 L1.1
MCU_DEC1: length 0.7
  TOP w0.1: C5.1 28.12,6.47 U1.B6
MCU_DEC2: length 0.6
  TOP w0.127: C7.1 26.41,7.42 U1.A3
MCU_DEC4: length 2.1
  TOP w0.2: L1.2 26.98,8.86 C6.1 26.98,7.43 26.81,7.27 U1.A4
MCU_P003: length 5.7
  TOP w0.1: U1.D6 27.75,6.21 28.35,6.21 28.56,6.42 28.56,7 28.9,7.34 30.43,7.34 30.84,7.75 31.75,7.75 TP8.1
MCU_P004: length 4.4
  L2 w0.1: v1(27.21,5.67) 27.55,5.67 28.07,5.15 28.07,2.9 28.81,2.16 v1(28.85,2.16)
MCU_P005: length 5.4
  TOP w0.1: U1.E6 27.73,5.78 27.73,5.78 27.93,5.98 28.45,5.98 28.79,6.32 28.79,6.9 29,7.11 30.54,7.11 30.94,7.52 31.65,7.52 TP10.1
MCU_P008: length 3.2
  TOP w0.1: U1.F6 27.73,5.16 27.9,4.99 27.9,4.17 TP2.1
MCU_P018: length 2.9
  L2 w0.1: v1(24.42,3.74) 24.82,3.74 25.64,4.55 25.64,5.36 25.95,5.67 v1(26.01,5.67)
MCU_P020: length 2
  TOP w0.1: TP1.1 24.72,4.2 25.37,4.2 26.01,4.84 U1.G2
MCU_PO17: length 4.9
  L2 w0.1: v1(28.35,1.58) 28.35,1.92 26.5,3.77 26.25,3.77 26.09,3.93 26.09,4.47 26.39,4.76 26.39,4.78 26.41,4.8 v1(26.41,5.27)
MCU_RESET: length 45.8
  TOP w0.1: v3(8.39,13.57) 8.39,14.21 10.39,16.21 23.09,16.21 J2.3 v1(25.19,16.85)
  L2 w0.1: v2(8.74,13.57) v3(8.39,13.57) ; v1(25.19,16.85) v2(25.52,16.98) ; v1(26.01,5.27) v2(26.01,4.92)
  L3 w0.1: v2(25.52,16.98) v3(25.52,16.62) ; v2(26.01,4.92) v3(26.44,4.92) ; v3(8.39,13.57) v2(8.74,13.57)
  BOTTOM w0.1: v3(8.39,13.57) 6.91,13.57 6.42,14.06 3,14.06 SW1.2 2.2,12.05 2.54,11.45 2.21,10.67 1.6,10.44 SW1.1 1.04,8.88 1.04,8.1 1.03,8.1 1.03,7.48 ; v3(26.44,4.92) 26.44,5.98 26.03,6.39 26.03,8.02 26.17,8.16 26.17,15.97 v3(25.52,16.62)
MCU_STATUS1: length 24.4
  TOP w0.1: 24.13,22.62 v1(24.13,22.57) ; v1(26.64,4.48) 26.64,4.49 26.81,4.66 U1.G4
  L2 w0.1: v2(23.7,22.58) 23.71,22.58 23.72,22.57 v1(24.13,22.57) ; v1(26.64,4.48) v2(26.47,4.15)
  L3 w0.1: v3(23.39,22.88) v2(23.7,22.58) ; v2(26.47,4.15) v3(26.18,3.93)
  BOTTOM w0.1: v3(23.39,22.88) 22.84,22.88 21.8,21.85 21.8,18.8 24.44,16.16 24.44,9.86 24.3,9.72 24.3,5.03 25.39,3.95 26.16,3.95 v3(26.18,3.93)
MCU_STATUS2: length 27.3
  L2 w0.1: v2(27.5,4.34) 27.5,4.39 26.81,5.07 v1(26.81,5.27) ; v1(24.1,23.93) v2(24.1,23.61)
  L3 w0.1: v3(27.75,4.1) 27.74,4.1 v2(27.5,4.34) ; v2(24.1,23.61) v3(24.1,23.95)
  BOTTOM w0.1: v3(27.75,4.1) 27.59,4.25 25.42,4.25 24.61,5.07 24.61,7.92 25,8.32 25,8.89 24.68,9.22 24.68,16.25 22.03,18.89 22.03,21.74 22.84,22.55 23.56,22.55 24.1,23.09 v3(24.1,23.95)
MCU_SWDCLK: length 15.4
  TOP w0.1: U1.G1 25.27,4.53 v1(25.03,4.53) ; J2.2 24.63,14.93 arc(24.49,14.76) 24.44,14.54 arc(24.47,14.38) 24.53,14.22 25.75,11.95 v1(25.75,11.91)
  L2 w0.1: v1(25.75,11.91) 25.74,11.92 25.74,11.94 25.52,12.16 v2(25.5,12.16) ; v1(25.03,4.53) v2(24.8,4.26)
  L3 w0.1: v3(25.58,5.02) 25.57,5.01 25.5,5.01 24.8,4.31 v2(24.8,4.26) ; v2(25.5,12.16) 25.26,12.4 v3(25.24,12.4)
  BOTTOM w0.1: v3(25.58,5.02) 25.06,5.53 25.06,7.69 25.34,7.97 25.34,7.97 25.72,8.35 25.72,11.92 v3(25.24,12.4)
MCU_SWDIO: length 13.6
  TOP w0.1: D2.K v1(26.23,12.42) J2.1 ; U1.F1 25.49,5.27 v1(25.18,4.96)
  L2 w0.1: v2(25.42,5.7) 25.42,5.43 25.18,5.19 v1(25.18,4.96) ; v1(26.23,12.42) v2(25.99,12.67)
  L3 w0.1: v2(25.42,5.7) 25.77,5.7 v3(25.97,5.5) ; v3(25.56,12.74) v2(25.99,12.67)
  BOTTOM w0.1: v3(25.56,12.74) 25.94,12.36 25.94,8.25 25.57,7.88 25.57,7.88 25.29,7.59 25.29,6.19 v3(25.97,5.5)
MCU_XL1: length 4.5
  TOP w0.1: v1(29.11,5.92) 29.36,5.67 29.36,5.66 29.77,5.25 29.95,5.25 Y1.1
  L2 w0.1: v1(29.11,5.92) 29.06,5.97 28.75,5.97 28.39,6.32 28.07,6.32 28.06,6.33 27.43,6.33 27.28,6.47 v1(27.21,6.47)
MCU_XL2: length 4.2
  TOP w0.1: Y1.2 29.63,5.06 29.19,5.5 28.86,5.5 v1(28.77,5.41)
  L2 w0.1: v1(28.77,5.41) 28.77,5.63 28.3,6.1 27.97,6.1 27.97,6.1 27.24,6.1 v1(27.21,6.07)
PP1800_EN: length 1.4
  BOTTOM w0.1: U3.4 R13.1 4.97,6.26 R18.1
PP1800_SENSORS: length 35.4
  TOP w0.2: v1(8.75,8.16) 9.32,8.16 v3(9.35,8.19) 18.33,8.19 v1(22.49,12.35)
  L2 w0.2: v1(22.49,12.35) v2(22.74,12.6)
  L2 w0.25: v2(9.35,7.84) v3(9.35,8.19) ; v2(8.75,7.8) v1(8.75,8.16)
  L3 w0.2: v2(22.74,12.6) 24.54,14.4 v3(29.31,14.4)
  L3 w0.25: v3(8.75,8.17) v2(8.75,7.8) ; v3(9.35,8.19) v2(9.35,7.84)
  BOTTOM w0.2: 8.76,8.19 v3(9.35,8.19) 9.35,7.85 R5.1 ; v3(29.31,14.4) 29.31,20.94 29.11,21.14 28.81,21.14 ; R20.2 7.57,9.34 U3.1 7.58,8.18 8.75,8.18
  BOTTOM w0.25: 8.75,8.18 8.76,8.19
PP3300_EN: length 1.4
  BOTTOM w0.1: U2.4 R12.1 4.74,16.52 R17.1
PP3300_SENSORS: length 20.4
  TOP w0.4: 20.02,23.44 R9.1 20.45,23.06 ; 24.31,19.8 J2.5 23.52,18.98 ; v3(2.14,7.48) 2.73,7.48 v3(4.16,8.91) ; 22.23,21.32 v1(22.23,21.76) 22.62,21.76 ; v1(8.61,18.37) 8.66,18.41 v3(9.21,18.41)
  L2 w0.4: v2(9.21,18.03) v3(9.21,18.41) ; v2(2.49,7.48) v3(2.14,7.48) ; v2(3.81,8.91) v3(4.16,8.91) ; v2(8.61,17.97) v1(8.61,18.37) ; v3(30.17,8.46) v2(30.17,8.85) v2(30.57,8.85) ; v2(6.43,9.35) v3(6.86,9.35)
  L3 w0.4: v3(8.61,18.35) v2(8.61,17.97) ; v2(30.57,8.85) v3(30.57,8.46) ; v2(6.43,9.35) v3(6.86,9.35) ; v3(4.16,8.91) v2(3.81,8.91) ; v3(9.21,18.41) v2(9.21,18.03) ; v3(2.14,7.48) v2(2.49,7.48)
  BOTTOM w0.25: v3(8.61,18.35) 8.6,18.37 C21.1 8.11,18.35 U2.1 ; R3.1 9.21,17.91 v3(9.21,18.41) 9.17,18.37 v1(8.61,18.37)
  BOTTOM w0.3: v3(28.34,20.22) 28.31,20.25 J3.9 28.31,21.8 28.09,22.02 R2.1 ; v3(25.77,22.67) v3(25.29,22.67)
  BOTTOM w0.4: 28.31,10.32 v3(30.17,8.46) v3(30.57,8.46) ; 1.75,7.48 v3(2.14,7.48)
  vias: v1(20.17,21.92) v1(20.17,21.61) v1(20.48,21.93) v1(20.47,21.6) v2(22.64,21.76) v2(23.05,21.77) v3(28.1,22.77) v3(28.1,22.25) v3(28.69,20.21)
PP3300_SENSORS_MCU: length 6.1
  TOP w0.127: U1.G6 27.57,4.83 27.57,3.78 v3(27.44,3.65)
  TOP w0.2: v1(27.93,7.41) 27.85,7.32 27.85,7.1 U1.A6 ; v3(28.6,7.75) 28.3,7.45 C19.1
  TOP w0.4: v3(28.6,7.75) v3(29.37,7.75) 29.38,7.74 v3(30.17,7.74)
  L2 w0.127: v3(27.44,3.65) v2(27.69,3.4)
  L3 w0.127: v2(27.69,3.4) v3(27.44,3.65) ; v2(29.82,7.74) v3(30.17,7.74) ; v2(28.95,7.75) v3(28.6,7.75) ; v2(29.37,7.4) v3(29.37,7.75)
PP3300_SENSORS_R: length 1.6
  BOTTOM w0.4: U3.6 C24.1 4.17,8.2 R19.2
PP_1800_ADJ: length 1.5
  BOTTOM w0.1: R6.1 R5.2 U3.2
PP_3300_ADJ: length 1.6
  BOTTOM w0.1: U2.2 8.28,17.7 R3.2 8.29,16.95 R4.1
PP_VBAT: length 22.8
  TOP w0.4: TP15.1 3.26,18.8 3.66,18.4 v1(4.67,18.4) v1(4.67,17.77) v3(4.74,17.77) 6.38,16.13 v3(6.38,11.47) ; v3(4.25,6.9) v1(5.95,8.59)
  L2 w0.4: v2(3.9,6.9) v3(4.25,6.9) ; v2(6.03,11.82) 6.03,11.49 v1(6.01,11.47) v3(6.38,11.47) v2(6.38,11.12) ; v2(4.22,18.4) v1(4.67,18.4) ; v2(4.22,17.77) v1(4.67,17.77) ; v1(5.95,8.59) v2(6.39,8.59)
  L3 w0.4: v2(6.39,8.59) v3(6.14,8.84) ; v3(6.38,11.47) v2(6.38,11.12) ; v3(6.38,11.47) v3(6.38,11.8) ; v3(6.38,11.47) 6.03,11.82 v2(6.03,11.82) ; v3(4.74,17.77) v2(4.22,17.77) ; v3(4.25,6.9) v2(3.9,6.9) ; v3(4.74,18.4) v2(4.22,18.4)
  BOTTOM w0.4: v3(6.14,8.84) 6.14,10.26 6.38,10.49 v3(6.38,11.47) ; v3(4.74,17.77) v3(4.74,18.4) 4.79,18.35 U2.6
PP_VBAT_SENSE: length 28
  TOP w0.4: v3(12.91,21.43) 12.2,20.71 4.87,20.71 4.29,21.29 TP16.1
  L2 w0.4: v2(11.89,22.45) v3(11.89,22.1) ; v2(12.87,23.2) v3(12.87,22.85) ; v2(12.09,2.59) v3(12.09,2.24) ; v2(13.87,20.88) v3(13.87,20.53) ; v2(10.9,5.47) v3(10.9,5.12) ; v2(10.97,21.54) v3(10.97,21.19) ; v2(15.06,1.57) v3(15.06,1.22) ; v2(14.12,4.51) v3(14.12,4.16) ; v2(14.13,2.55) v3(14.13,2.2) ; v2(10.95,19.89) v3(10.95,19.54) ; v2(15.03,3.56) v3(15.03,3.21) ; v2(10.83,1.62) v3(10.83,1.27) ; v2(12.88,19.91) v3(12.88,19.56) ; v2(13.84,22.57) v3(13.84,22.22) ; v2(12.06,4.48) v3(12.06,4.13) ; v2(12.92,3.5) v3(12.92,3.15) ; v2(12.98,1.63) v3(12.98,1.28) ; v2(10.98,3.59) v3(10.98,3.24) ; v2(11.97,20.54) v3(11.97,20.19) ; v2(14.7,21.53) v3(14.7,21.18) ; v3(12.91,21.43) v2(12.91,21.78) ; v2(12.98,5.44) v3(12.98,5.09) ; v2(14.74,23.24) v3(14.74,22.89) ; v2(10.98,23.18) v3(10.98,22.83) ; v2(14.96,5.52) v3(14.96,5.17)
  L3 w0.4: v2(10.97,21.54) v3(10.97,21.19) ; v3(10.83,1.27) v2(10.83,1.62) ; v2(10.95,19.89) v3(10.95,19.54) ; v2(14.74,23.24) v3(14.74,22.89) ; v3(14.96,5.17) v2(14.96,5.52) ; v2(11.89,22.45) v3(11.89,22.1) ; v2(12.88,19.91) v3(12.88,19.56) ; v2(12.06,4.48) v3(12.06,4.13) ; v2(14.94,19.96) v3(14.94,19.61) ; v3(14.13,2.2) v2(14.13,2.55) ; v2(13.87,20.88) v3(13.87,20.53) ; v2(13.84,22.57) v3(13.84,22.22) ; v2(10.98,23.18) v3(10.98,22.83) ; v2(12.92,3.5) v3(12.92,3.15) ; v3(15.03,3.21) v2(15.03,3.56) ; v2(12.98,5.44) v3(12.98,5.09) ; v2(10.9,5.47) v3(10.9,5.12) ; v2(11.97,20.54) v3(11.97,20.19) ; v3(15.06,1.22) v2(15.06,1.57) ; v2(12.91,21.78) v3(12.91,21.43) ; v2(14.7,21.53) v3(14.7,21.18) ; v3(12.09,2.24) v2(12.09,2.59) ; v2(10.98,3.59) v3(10.98,3.24) ; v3(12.98,1.28) v2(12.98,1.63) ; v2(12.87,23.2) v3(12.87,22.85) ; v2(14.12,4.51) v3(14.12,4.16)
  vias: v3(10.3,20.83) v3(10.3,19.92) v3(10.32,19) v3(10.32,18) v3(10.32,17) v3(10.32,16) v3(10.32,15) v3(10.32,14) v3(10.32,13) v3(10.32,12) v3(10.32,11) v3(10.32,10) v3(10.31,9.01) v3(10.31,8.01) v3(10.31,7.01) v3(10.31,6.01) v3(10.31,5.01) v3(10.31,4.01)
SCL_3300: length 20.4
  TOP w0.1: U1.G5 27.21,4.56 27.02,4.37 v1(27.02,4.31)
  L2 w0.1: v1(27.02,4.31) v2(27.02,3.96)
  L3 w0.1: v3(27.02,4.79) v2(27.02,3.96)
  BOTTOM w0.1: R1.2 26.81,22.35 J3.6 26.81,8.48 26.26,7.92 26.26,6.53 27.02,5.76 v3(27.02,4.79)
SDA_3300: length 19.7
  L2 w0.1: v2(27.54,4.93) 27.21,5.26 v1(27.21,5.27)
  L3 w0.1: v3(27.8,4.69) 27.78,4.69 27.77,4.71 27.76,4.71 v2(27.54,4.93)
  BOTTOM w0.1: v3(27.8,4.69) 27.8,5.33 26.48,6.65 26.48,7.83 27.31,8.66 J3.7 27.31,22.61 R2.2
XC1: length 1.8
  TOP w0.1: 24.68,7 25.43,7 25.56,6.87 U1.A1 ; 24.68,7 Y2.3 ; 24.68,7 C9.1
XC2: length 3.3
  TOP w0.1: U1.A2 26.01,7.06 25.88,7.19 25.56,7.19 25.26,7.49 25.26,8.22 25.62,8.58 Y2.1 25.78,8.58 C8.1

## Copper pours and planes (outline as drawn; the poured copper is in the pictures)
GND on TOP: 5.14,24.42 6.69,24.75 26.1,24.75 27.65,24.42 28.92,23.47 31.08,20.34 32.48,16.8 32.54,15.69 32.16,14.64 31.54,12.5 32.16,10.36 32.54,9.31 32.48,8.2 31.08,4.66 28.92,1.53 27.65,0.58 26.1,0.25 6.69,0.25 5.14,0.58 3.87,1.53 1.71,4.66 0.31,8.2 0.25,9.31 0.63,10.36 1.24,12.5 0.63,14.64 0.25,15.69 0.31,16.8 1.71,20.34 3.87,23.47 ; 3 cut-outs
GND on BOTTOM, L2, L3: 5.14,24.42 6.69,24.75 26.1,24.75 27.65,24.42 28.92,23.47 31.08,20.34 32.48,16.8 32.54,15.69 32.16,14.64 31.54,12.5 32.16,10.36 32.54,9.31 32.48,8.2 31.08,4.66 28.92,1.53 27.65,0.58 26.1,0.25 6.69,0.25 5.14,0.58 3.87,1.53 1.71,4.66 0.31,8.2 0.25,9.31 0.63,10.36 1.24,12.5 0.63,14.64 0.25,15.69 0.31,16.8 1.71,20.34 3.87,23.47
PP3300_SENSORS on TOP: outline of 120 points within 1.83,7.14 25.46,23.66
PP3300_SENSORS on L2: 20.21,22.1 20.07,22.04 20.01,21.9 20.01,21.63 20.07,21.49 20.21,21.43 23.18,21.43 23.32,21.49 23.38,21.63 23.38,21.9 23.32,22.04 23.18,22.1
PP3300_SENSORS on L3: 30.17,9.05 30.03,8.99 29.97,8.85 29.97,8.46 30.03,8.32 30.17,8.26 30.57,8.26 30.72,8.32 30.77,8.46 30.77,8.85 30.72,8.99 30.57,9.05
PP3300_SENSORS on L3: 8.62,18.61 8.48,18.55 8.42,18.41 8.42,17.97 8.48,17.83 8.62,17.77 9.21,17.77 9.36,17.83 9.41,17.97 9.41,18.41 9.36,18.55 9.21,18.61
PP3300_SENSORS_MCU on BOTTOM: 28.3,7.87 28.3,7.55 28.79,7.06 28.79,4.5 28.16,3.87 28.16,3.86 27.31,3.86 27.14,3.69 27.14,3.4 27.26,3.28 28.49,3.28 30.49,5.28 30.49,7.76 30.22,8.03 28.47,8.03
PP3300_SENSORS_MCU on L2: 30.43,7.19 30.43,7.99 28.47,7.99 28.19,7.71 27.9,7.71 27.71,7.52 27.71,7.24 27.76,7.19
PP3300_SENSORS_MCU on L3: 28.58,7.99 28.44,7.93 28.38,7.79 28.38,7.39 28.44,7.25 28.58,7.19 30.23,7.19 30.38,7.25 30.43,7.39 30.43,7.79 30.38,7.93 30.23,7.99
PP_VBAT on L2, L3: 6.03,12.02 5.89,11.96 5.83,11.82 5.83,11.12 5.89,10.98 6.03,10.92 6.38,10.92 6.52,10.98 6.58,11.12 6.58,11.82 6.52,11.96 6.38,12.02
PP_VBAT_SENSE on BOTTOM: 7.58,11.9 7.58,11.07 9.89,11.07 9.89,11.9
PP_VBAT_SENSE on BOTTOM: 10.07,23.52 15.14,23.52 15.43,23.23 15.43,19.5 15,19.07 11.36,19.07 11.34,19.09 10.76,18.51 10.76,6.97 10.74,6.95 11.36,6.33 15.19,6.33 15.89,5.63 15.89,1.22 15.32,0.65 10.64,0.65 9.71,1.58 9.71,10.76 9.35,11.12 9.35,11.84 9.91,12.4 9.91,23.36
PP_VBAT_SENSE on L2: 10.59,23.88 10.45,23.82 10.39,23.68 10.39,19.09 10.45,18.95 10.59,18.89 15.24,18.89 15.39,18.95 15.44,19.09 15.44,23.68 15.39,23.82 15.24,23.88
PP_VBAT_SENSE on L2: 10.71,5.83 10.57,5.77 10.51,5.63 10.51,1.04 10.57,0.9 10.71,0.84 15.36,0.84 15.51,0.9 15.56,1.04 15.56,5.63 15.51,5.77 15.36,5.83

Small or netless copper shapes (teardrops, artwork), in the pictures only: 1 on TOP, 1 on BOTTOM, 2 on L3

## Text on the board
XSECTION_CHART: *  SURFACE | * SOLDERMASK_TOP MASK | L1 TOP CONDUCTOR | *  DIELECTRIC | L2 L2 CONDUCTOR | L3 L3 CONDUCTOR | L4 BOTTOM CONDUCTOR | * SOLDERMASK_BOTTOM MASK | DESIGN CROSS SECTION CHART | ___________________________ | TOTAL THICKNESS 0.5372 MM | 1-2 | 2-3 | 3-4
User.8: L4
User.9: L5
User.10: L6
User.11: L7
User.12: FGF_TOP
User.13: FGF_BOT
User.14: ADHS_TOP
User.15: ADHS_BOT
User.16: ADHS_LINER_TOP
User.17: ADHS_LINER_BOT
User.18: CONDUCTIVE_ADHS_TOP
User.19: CONDUCTIVE_ADHS_BOT
User.20: ADHS_ABOVE_STF_TOP
User.21: ADHS_ABOVE_STF_BOT
User.22: PIC_TOP
User.23: PIC_BOT
User.24: LPI_TOP
User.25: LPI_BOT
User.26: CFML_COAT_TOP
User.27: CFML_COAT_BOT
User.28: EMI_SHIELD_TOP
User.29: EMI_SHIELD_BOT
User.30: BEND_AREA
User.31: COVERLAY_TOP
User.32: COVERLAY_BOT
User.33: STF_TOP
User.34: STF_BOT
User.35: STF_METAL_TOP
User.36: STF_METAL_BOT
User.37: ASSEMBLY_TOP
User.38: ASSEMBLY_BOT
User.41: SOLDERPASTE_TOP
User.42: SOLDERPASTE_BOT
User.43: SF_OSP_TOP
User.44: SF_OSP_BOT
